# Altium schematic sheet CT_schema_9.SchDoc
size 297 x 239 mm
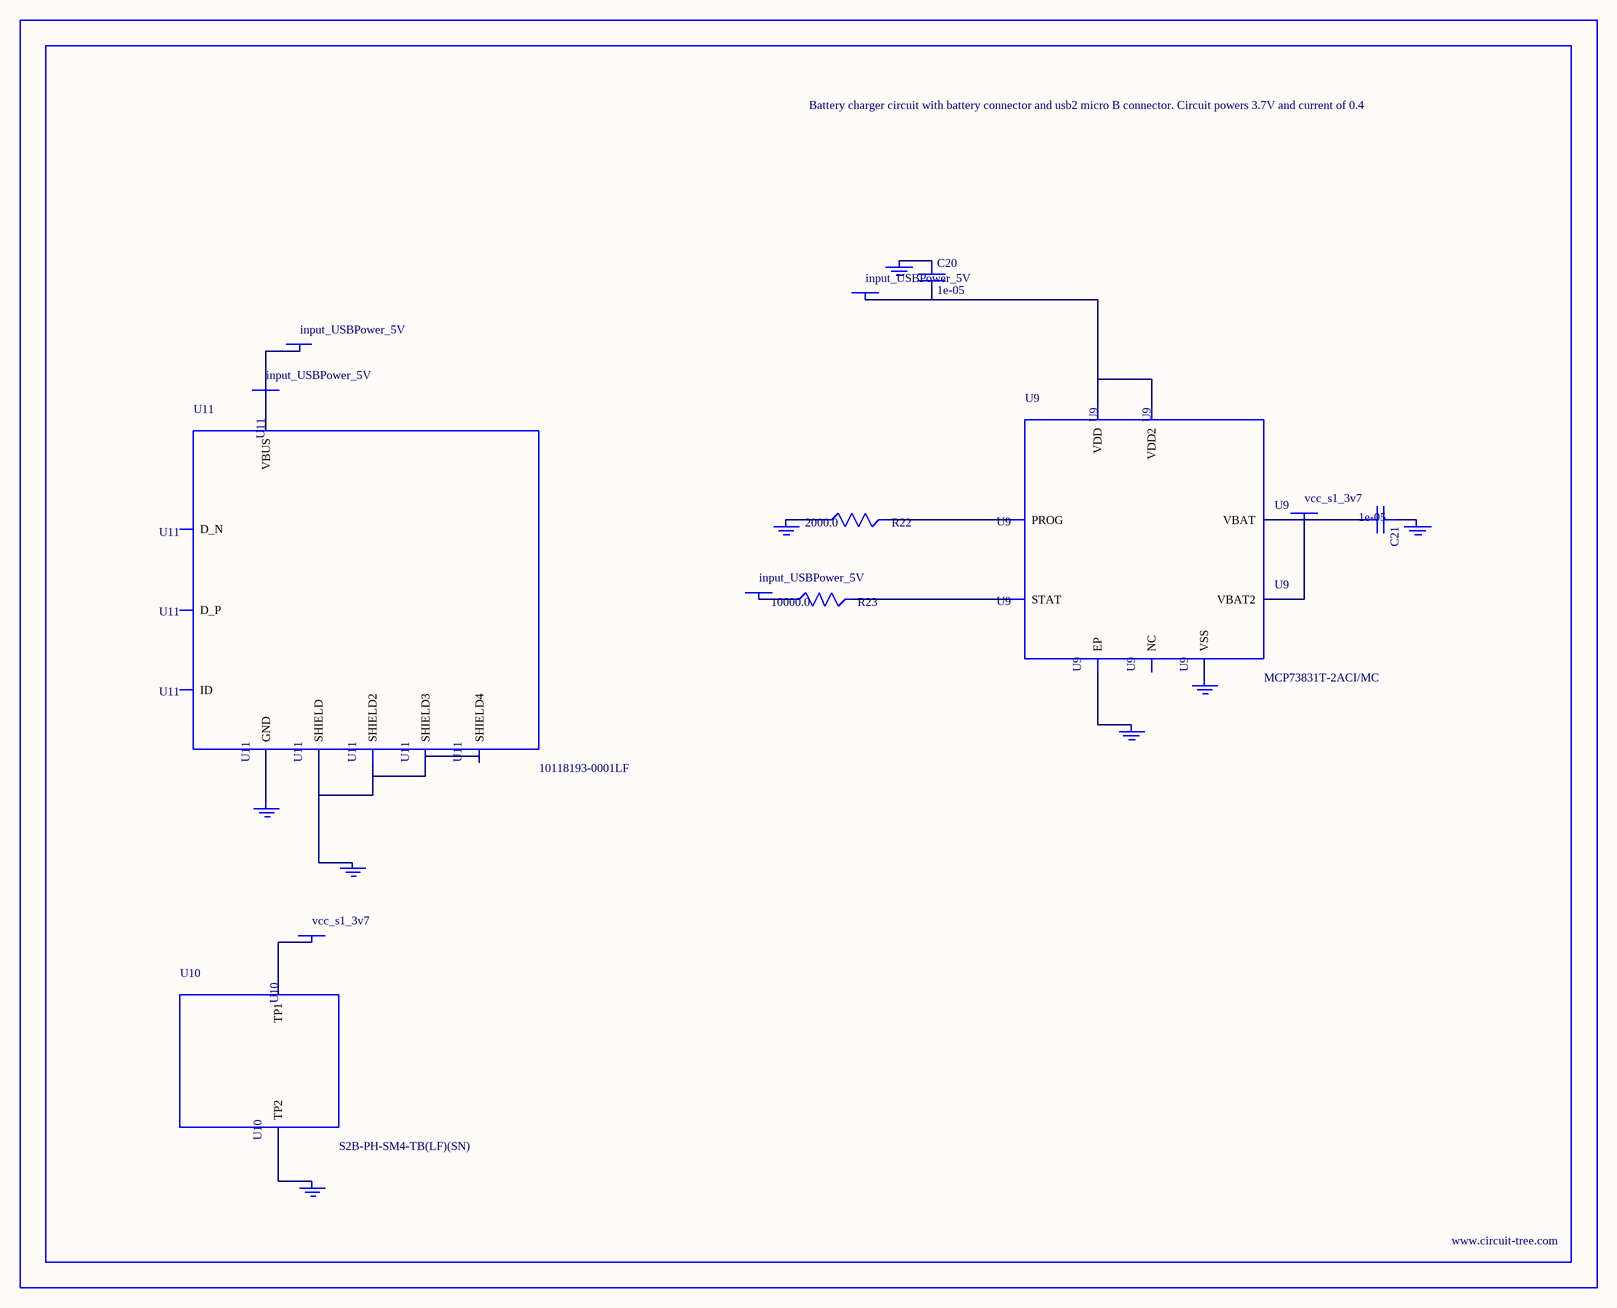
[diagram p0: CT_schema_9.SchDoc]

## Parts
BORDER8  (no value)
C20  1e-05  [C1206]
C21  1e-05  [C1206]
GND_INSTANCE_8_0  (no value)
GND_INSTANCE_8_1  (no value)
GND_INSTANCE_8_2  (no value)
GND_INSTANCE_8_3  (no value)
GND_INSTANCE_8_4  (no value)
GND_INSTANCE_8_5  (no value)
GND_INSTANCE_8_6  (no value)
GND_INSTANCE_8_7  (no value)
POWER_INSTANCE_8_0  input_USBPower_5V
POWER_INSTANCE_8_1  input_USBPower_5V
POWER_INSTANCE_8_2  vcc_s1_3v7
POWER_INSTANCE_8_3  vcc_s1_3v7
POWER_INSTANCE_8_4  input_USBPower_5V
POWER_INSTANCE_8_5  input_USBPower_5V
R22  2000.0  [R0603]
R23  10000.0  [R0603]
U9  MCP73831T-2ACI/MC  [DFN8_2X3MC]
U10  S2B-PH-SM4-TB(LF)(SN)  [JST-2-SMD]
U11  10118193-0001LF  [FCI_10118193-0001LF]

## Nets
NetC20_1: C20.1 GND_INSTANCE_8_0.0(GND)
NetC20_2: C20.2 POWER_INSTANCE_8_0.0(PWR) U9.1(VDD) U9.2(VDD2)
NetC21_1: C21.1 GND_INSTANCE_8_1.0(GND)
NetC21_2: C21.2 POWER_INSTANCE_8_2.0(PWR) U9.3(VBAT) U9.4(VBAT2)
NetGND_INSTANCE_8_2_0: GND_INSTANCE_8_2.0(GND) R22.1
NetGND_INSTANCE_8_3_0: GND_INSTANCE_8_3.0(GND) U9.9(EP)
NetGND_INSTANCE_8_4_0: GND_INSTANCE_8_4.0(GND) U9.6(VSS)
NetGND_INSTANCE_8_5_0: GND_INSTANCE_8_5.0(GND) U10.2(TP2)
NetGND_INSTANCE_8_6_0: GND_INSTANCE_8_6.0(GND) U11.6(SHIELD) U11.7(SHIELD2) U11.8(SHIELD3) U11.9(SHIELD4)
NetGND_INSTANCE_8_7_0: GND_INSTANCE_8_7.0(GND) U11.5(GND)
NetPOWER_INSTANCE_8_1_0: POWER_INSTANCE_8_1.0(PWR) R23.1
NetPOWER_INSTANCE_8_3_0: POWER_INSTANCE_8_3.0(PWR) U10.1(TP1)
NetPOWER_INSTANCE_8_4_0: POWER_INSTANCE_8_4.0(PWR) POWER_INSTANCE_8_5.0(PWR) U11.1(VBUS)
NetR22_2: R22.2 U9.8(PROG)
NetR23_2: R23.2 U9.5(STAT)

Not connected (* = marked no-connect by the designer): U9 7(NC); U11 2(D_N) 3(D_P) 4(ID)

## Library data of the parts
BORDER8 = BORDER_PAGE8
C20 C21 = C1206C106K3RACTU
GND_INSTANCE_8_0-GND_INSTANCE_8_7 = GND
POWER_INSTANCE_8_0-POWER_INSTANCE_8_5 = PWR
R22 = RC0603JR-072KL
R23 = RC0603JR-0710KL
